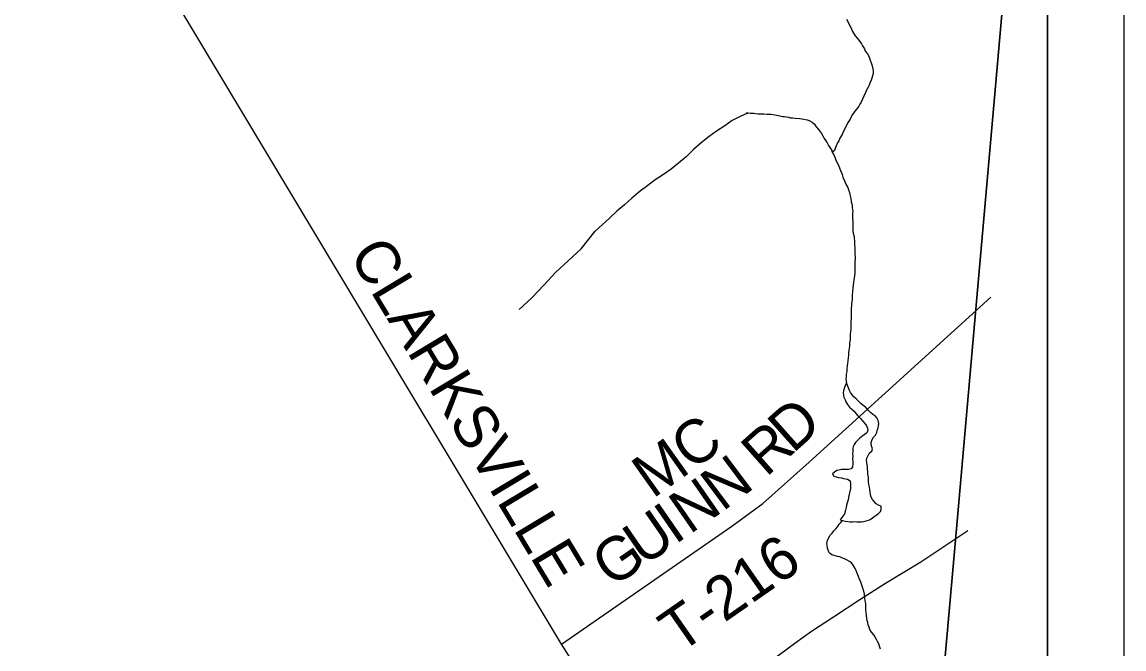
# Model space of a CAD drawing. Extents: x 0.4 to 34.4, y -2.1 to 19.9.
# Drawn here: x 8.46 to 9.9, y 13.838 to 14.658 of the extents above; entities that cross this region are included whole.
import ezdxf

# ---------------------------------------------------------------- set-up
doc = ezdxf.new("R2010")
doc.units = 0
for name, color, linetype in [('GM_X_Adjacent_County', 7, 'Continuous'), ('GM_X_County', 7, 'Continuous'), ('GM_X_County_Road', 7, 'Continuous'), ('GM_X_County_Road_Text', 7, 'Continuous'), ('GM_X_Minor_Lake', 7, 'Continuous'), ('GM_X_Minor_River', 7, 'Continuous'), ('GM_X_Township', 7, 'Continuous'), ('GM_X_Township_Road', 7, 'Continuous'), ('GM_X_Township_Road_Text', 7, 'Continuous'), ('GM_X_US_Route', 7, 'Continuous'), ('SH_Data', 7, 'Continuous')]:
    doc.layers.add(name, color=color, linetype=linetype)

msp = doc.modelspace()

# ---------------------------------------------------------------- linework, layer by layer
at = {"layer": 'GM_X_Adjacent_County'}
for points in [[(9.5074, 12.0357), (9.8001, 12.0357), (9.8001, 15.3423)], [(9.8001, 15.3423), (9.7654, 14.9495), (9.706, 14.2776), (9.6797, 13.9803), (9.6042, 13.1277), (9.5589, 12.6168), (9.5074, 12.0357)]]:
    msp.add_lwpolyline(points, dxfattribs=at)
at = {"layer": 'GM_X_County'}
msp.add_lwpolyline([(9.5074, 12.0357), (9.5589, 12.6168), (9.6042, 13.1277), (9.6797, 13.9803), (9.706, 14.2776), (9.7654, 14.9495), (9.8001, 15.3423)], dxfattribs=at)
at = {"layer": 'GM_X_County_Road'}
msp.add_lwpolyline([(9.2621, 13.6921), (9.2169, 13.7627), (9.1648, 13.8442), (8.4596, 15.0199)], dxfattribs=at)
at = {"layer": 'GM_X_Minor_Lake'}
for points in [[(9.5637, 14.0844), (9.5641, 14.0874), (9.5656, 14.0912), (9.5676, 14.0946), (9.5707, 14.0968), (9.5715, 14.0995), (9.5704, 14.1021), (9.5696, 14.1052), (9.5697, 14.1082), (9.5709, 14.112), (9.5728, 14.115), (9.5751, 14.1176), (9.5771, 14.121), (9.5775, 14.1237), (9.5787, 14.1271), (9.5791, 14.1297), (9.5795, 14.1328), (9.5788, 14.1366), (9.577, 14.1404), (9.5744, 14.1431), (9.5717, 14.1446), (9.5687, 14.1473), (9.5661, 14.1497), (9.5631, 14.1531), (9.5605, 14.1554), (9.5567, 14.1585), (9.5526, 14.1624), (9.55, 14.1651), (9.547, 14.1678), (9.5447, 14.1705), (9.5425, 14.1735), (9.5407, 14.177), (9.5399, 14.1796), (9.5388, 14.1823), (9.5374, 14.1858), (9.5358, 14.1824), (9.5342, 14.1786), (9.5334, 14.1756), (9.533, 14.1729), (9.5333, 14.1699), (9.5341, 14.1672), (9.5355, 14.1638), (9.5366, 14.1611), (9.5385, 14.1576), (9.5415, 14.1542), (9.5445, 14.1515), (9.5475, 14.1488), (9.5497, 14.1461), (9.5523, 14.143), (9.5553, 14.1396), (9.5583, 14.1361), (9.5613, 14.133), (9.5635, 14.1296), (9.565, 14.1269), (9.5653, 14.1235), (9.5642, 14.1208), (9.5603, 14.1178), (9.5576, 14.116), (9.5546, 14.1134), (9.5519, 14.1107), (9.5492, 14.1081), (9.5476, 14.1055), (9.5461, 14.1029), (9.5456, 14.1002), (9.5456, 14.096), (9.5452, 14.0934), (9.5455, 14.0899), (9.5454, 14.0862), (9.5458, 14.0835), (9.5457, 14.0801), (9.5453, 14.0763), (9.5434, 14.0736), (9.5399, 14.0726), (9.5373, 14.0726), (9.5342, 14.0726), (9.5308, 14.0727), (9.5274, 14.072), (9.5247, 14.0713), (9.5217, 14.069), (9.519, 14.0668), (9.5208, 14.0641), (9.5239, 14.0629), (9.5269, 14.0621), (9.5307, 14.0617), (9.5333, 14.0609), (9.536, 14.0605), (9.5386, 14.06), (9.542, 14.0577), (9.5427, 14.0539), (9.5427, 14.0505), (9.5426, 14.0478), (9.5418, 14.0441), (9.541, 14.0403), (9.5402, 14.0361), (9.5394, 14.0331), (9.5382, 14.0289), (9.5374, 14.0259), (9.537, 14.0232), (9.5362, 14.0194), (9.5346, 14.0149), (9.5291, 14.007)], [(9.5683, 14.0073), (9.5763, 14.0128), (9.5794, 14.015), (9.5817, 14.0177), (9.5829, 14.0203), (9.5829, 14.0249), (9.5803, 14.0257), (9.5761, 14.028), (9.5735, 14.0307), (9.5713, 14.0334), (9.5698, 14.0364), (9.5687, 14.0395), (9.5684, 14.0429), (9.5677, 14.0463), (9.5673, 14.0494), (9.5666, 14.0532), (9.5663, 14.0566), (9.566, 14.0593), (9.566, 14.0627), (9.5653, 14.0665), (9.5653, 14.0699), (9.565, 14.073), (9.5647, 14.0756), (9.5643, 14.0787), (9.564, 14.0817), (9.5637, 14.0844)], [(9.5291, 14.007), (9.5322, 14.0058), (9.5356, 14.005), (9.539, 14.0046), (9.5416, 14.0042), (9.5451, 14.0041), (9.5485, 14.0045), (9.5511, 14.0044), (9.5538, 14.0044), (9.5572, 14.0043), (9.5599, 14.0047), (9.5633, 14.0054), (9.5663, 14.0065), (9.5683, 14.0073)]]:
    msp.add_lwpolyline(points, dxfattribs=at)
at = {"layer": 'GM_X_Minor_River'}
for points in [[(9.5372, 14.6613), (9.5394, 14.6574), (9.5416, 14.6528), (9.5435, 14.6498), (9.5453, 14.6452), (9.5487, 14.6398), (9.5517, 14.6364), (9.555, 14.6322), (9.5569, 14.6291), (9.5583, 14.6264), (9.561, 14.6226), (9.562, 14.6195), (9.565, 14.6161), (9.5665, 14.613), (9.5676, 14.6103), (9.5683, 14.6077), (9.5698, 14.6042), (9.5709, 14.6004), (9.572, 14.5966), (9.5723, 14.5935), (9.5723, 14.5905), (9.5715, 14.5875), (9.5707, 14.5845), (9.5695, 14.5818), (9.5679, 14.578), (9.5671, 14.575), (9.5659, 14.5724), (9.5636, 14.5686), (9.5624, 14.5656), (9.5601, 14.5607), (9.5585, 14.5569), (9.5566, 14.5531), (9.555, 14.5505), (9.5535, 14.5479), (9.5511, 14.5441), (9.5484, 14.5411), (9.5453, 14.537), (9.5434, 14.5336), (9.5422, 14.5309), (9.5395, 14.5268), (9.5371, 14.5219), (9.5352, 14.5181), (9.5336, 14.5151), (9.5317, 14.5106), (9.5289, 14.5057), (9.5274, 14.5026), (9.5258, 14.5), (9.5243, 14.4966), (9.5231, 14.4936), (9.5215, 14.4898), (9.5188, 14.4876)], [(9.4064, 14.5391), (9.408, 14.5385), (9.3985, 14.5342), (9.3881, 14.5291), (9.3782, 14.5221), (9.3674, 14.5151), (9.3578, 14.5081), (9.3474, 14.4999), (9.3374, 14.491), (9.3277, 14.4814), (9.3177, 14.4732), (9.3081, 14.4655), (9.2969, 14.4573), (9.2873, 14.4515), (9.2777, 14.4441), (9.2677, 14.4367), (9.2569, 14.4274), (9.2472, 14.4189), (9.2372, 14.4104), (9.2276, 14.4015), (9.2179, 14.3925), (9.209, 14.3844)], [(9.4064, 14.5391), (9.4087, 14.5389), (9.4117, 14.5384), (9.4162, 14.5384), (9.4189, 14.5383), (9.4219, 14.5379), (9.4253, 14.5379), (9.4295, 14.5378), (9.4337, 14.5374), (9.4364, 14.5373), (9.439, 14.5373), (9.4439, 14.5365), (9.4504, 14.5352), (9.4538, 14.5344), (9.4564, 14.534), (9.4591, 14.5336), (9.4617, 14.5332), (9.4644, 14.5324), (9.467, 14.5324), (9.4705, 14.5319), (9.4758, 14.5315), (9.4792, 14.531), (9.4818, 14.5306), (9.486, 14.5298), (9.4894, 14.5286), (9.4924, 14.5267), (9.4954, 14.5244), (9.4976, 14.5205), (9.501, 14.5174), (9.5047, 14.5121), (9.507, 14.5082), (9.5084, 14.5056), (9.5103, 14.5025), (9.5122, 14.4998), (9.514, 14.4964), (9.5155, 14.4937), (9.5177, 14.4906), (9.5188, 14.4876), (9.521, 14.4841), (9.5221, 14.4811), (9.5236, 14.4772), (9.5269, 14.4707), (9.5288, 14.4658), (9.5317, 14.4585), (9.5328, 14.4551), (9.5346, 14.4501), (9.5365, 14.4459), (9.5391, 14.4413), (9.5398, 14.4383), (9.5412, 14.4348), (9.5416, 14.4322)], [(9.5416, 14.4322), (9.543, 14.4272), (9.5437, 14.4227), (9.5444, 14.42), (9.5448, 14.4173), (9.5448, 14.4147), (9.5455, 14.4105), (9.5454, 14.4078), (9.5454, 14.4048), (9.5453, 14.4014), (9.5456, 14.3972), (9.5456, 14.3934), (9.5458, 14.3846), (9.5462, 14.3816), (9.5473, 14.3774), (9.5479, 14.3694), (9.5479, 14.3668), (9.5482, 14.3626), (9.5485, 14.3554), (9.5488, 14.3493), (9.5483, 14.3428), (9.5482, 14.339), (9.5482, 14.3352), (9.5481, 14.3299), (9.5477, 14.3258), (9.5469, 14.3208), (9.5464, 14.317), (9.546, 14.314), (9.5456, 14.3094), (9.5451, 14.3053), (9.5447, 14.3003), (9.5446, 14.2947), (9.5441, 14.2897), (9.5441, 14.2867), (9.5437, 14.2837), (9.5436, 14.2802), (9.5436, 14.2772), (9.5435, 14.2745), (9.5435, 14.2719), (9.5435, 14.2692), (9.543, 14.2662), (9.543, 14.2632), (9.5429, 14.2594), (9.5429, 14.2556), (9.5425, 14.2525), (9.5424, 14.2499), (9.542, 14.2423), (9.5415, 14.2385), (9.5415, 14.2339), (9.5406, 14.2286), (9.5402, 14.2248), (9.5401, 14.2218), (9.5397, 14.2191), (9.5393, 14.2146), (9.5389, 14.2112), (9.5384, 14.2082), (9.538, 14.2047), (9.5379, 14.2006), (9.5371, 14.1972), (9.5371, 14.1934), (9.5367, 14.1907), (9.5374, 14.1858)], [(9.1093, 14.2818), (9.126, 14.2971), (9.1416, 14.3136), (9.1569, 14.3304), (9.174, 14.3461), (9.1904, 14.361), (9.209, 14.3844)], [(9.5583, 13.9189), (9.5561, 13.9254), (9.5546, 13.9292), (9.5532, 13.933), (9.551, 13.938), (9.5499, 13.9406), (9.5487, 13.9433), (9.5462, 13.9475), (9.5439, 13.9506), (9.5413, 13.9525), (9.5383, 13.9541), (9.5349, 13.9557), (9.5315, 13.9572), (9.5285, 13.9584), (9.5258, 13.9588), (9.5224, 13.96), (9.5182, 13.9612), (9.5152, 13.9632), (9.5138, 13.9658), (9.5127, 13.97), (9.512, 13.9735), (9.5116, 13.9761), (9.5124, 13.9799), (9.5144, 13.9837), (9.5159, 13.9867), (9.5186, 13.9893), (9.521, 13.9923), (9.5233, 13.9953), (9.5256, 13.9979), (9.5279, 14.001), (9.5302, 14.0036), (9.5322, 14.0058)], [(9.5818, 13.8377), (9.5807, 13.8415), (9.5796, 13.8449), (9.5778, 13.8476), (9.5767, 13.8503), (9.5748, 13.8533), (9.573, 13.8564), (9.57, 13.8599), (9.5681, 13.8633), (9.567, 13.8664), (9.5659, 13.8698), (9.5652, 13.8725), (9.5645, 13.8751), (9.5638, 13.8778), (9.5635, 13.882), (9.5631, 13.8862), (9.5628, 13.8888), (9.5628, 13.8919), (9.5625, 13.8949), (9.5625, 13.8976), (9.5618, 13.901), (9.5615, 13.9044), (9.5611, 13.9071), (9.5608, 13.9097), (9.5601, 13.9135), (9.559, 13.9162), (9.5583, 13.9189)]]:
    msp.add_lwpolyline(points, dxfattribs=at)
at = {"layer": 'GM_X_Township'}
msp.add_lwpolyline([(9.5074, 12.0357), (9.5589, 12.6168), (9.6042, 13.1277), (9.6797, 13.9803), (9.706, 14.2776), (9.7654, 14.9495), (9.8001, 15.3423)], dxfattribs=at)
at = {"layer": 'GM_X_Township_Road'}
msp.add_lwpolyline([(9.1648, 13.8442), (9.3873, 13.9985), (9.4279, 14.0282), (9.4886, 14.0824), (9.7259, 14.2981)], dxfattribs=at)
at = {"layer": 'GM_X_US_Route'}
msp.add_lwpolyline([(9.4397, 13.8232), (9.4698, 13.8456), (9.4917, 13.8614), (9.5206, 13.8801), (9.5548, 13.9027), (9.5886, 13.9239), (9.6347, 13.952), (9.696, 13.9931)], dxfattribs=at)
at = {"layer": 'SH_Data'}
for p, q in [((9.9001, 18.9357), (9.9001, 11.9357)), ((9.8001, 18.8357), (9.8001, 12.0357))]:
    msp.add_line(p, q, dxfattribs=at)

# ---------------------------------------------------------------- texts
at = {"layer": 'GM_X_County_Road_Text'}
msp.add_text('CLARKSVILLE', height=0.056818, rotation=300.9813, dxfattribs=at).set_placement((8.886, 14.3536))
at = {"layer": 'GM_X_Township_Road_Text'}
for s, height, rotation, p in [('D', 0.0568, 41.6921, (9.4672, 14.0928)), ('C', 0.0568, 36.0482, (9.3349, 14.0699)), ('R', 0.0568, 41.5619, (9.4322, 14.0618)), ('M', 0.0568, 35.3303, (9.284, 14.0338)), ('N', 0.0568, 36.8819, (9.3752, 14.0169)), ('N', 0.0568, 34.7543, (9.3322, 13.9871)), ('U', 0.0568, 34.6611, (9.2718, 13.9453)), ('I', 0.0568, 34.6794, (9.313, 13.9738)), ('G', 0.0568, 34.664, (9.2307, 13.9169)), ('T-216', 0.05682, 34.8583, (9.3189, 13.8311))]:
    msp.add_text(s, height=height, rotation=rotation, dxfattribs=at).set_placement(p)

doc.saveas('drawing.dxf')
